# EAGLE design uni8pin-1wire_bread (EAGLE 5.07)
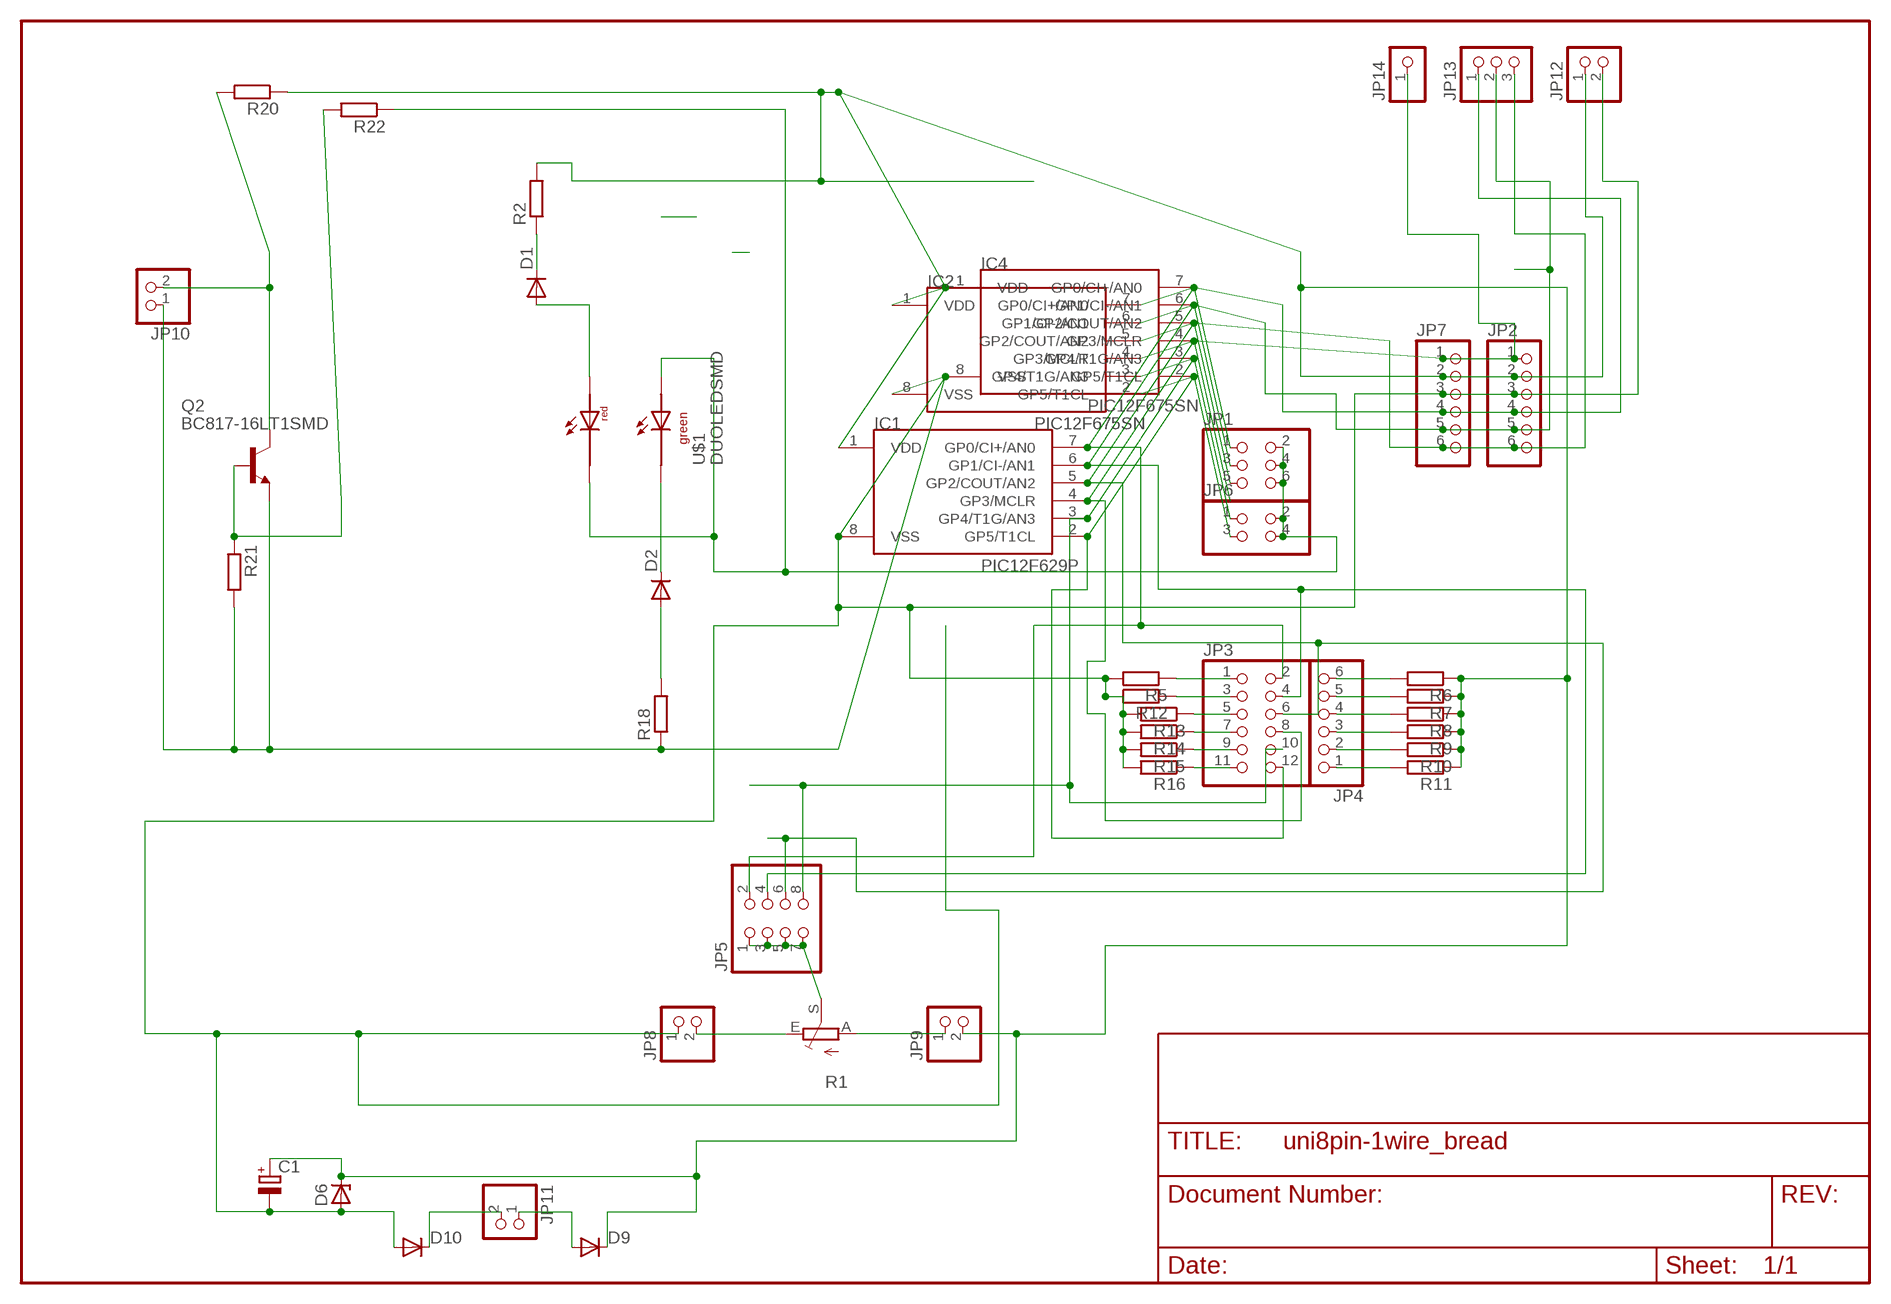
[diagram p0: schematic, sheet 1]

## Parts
C1  CPOL-EUE2.5-5  [E2,5-5]
D1  DIODE-MINIMELF  [MINIMELF]
D2  DIODE-MINIMELF  [MINIMELF]
D6  ZENER-DIODEZD-2.5  [ZDIO-2.5]
D9  DIODE-D-5  [D-5]
D10  DIODE-D-5  [D-5]
IC1  PIC12F629P  [DIL8]
IC2  PIC12F675SN  [SO-08]
IC4  PIC12F675SN  [SO-08]
JP1  PINHD-2X3  [2X03]
JP2  PINHD-1X6  [1X06]
JP3  PINHD-2X6  [2X06]
JP4  PINHD-1X6  [1X06]
JP5  PINHD-2X4  [2X04]
JP6  PINHD-2X2  [2X02]
JP7  PINHD-1X6  [1X06]
JP8  PINHD-1X2  [1X02]
JP9  PINHD-1X2  [1X02]
JP10  PINHD-1X2  [1X02]
JP11  PINHD-1X2  [1X02]
JP12  PINHD-1X2  [1X02]
JP13  PINHD-1X3  [1X03]
JP14  PINHD-1X1  [1X01]
Q2  BC817-16LT1SMD  [SOT23-BEC]
R1  TRIM_EU-RAND160  [RANDL]
R2  R-EU_R1206  [R1206]
R5  R-EU_R1206  [R1206]
R6  R-EU_R1206  [R1206]
R7  R-EU_R1206  [R1206]
R8  R-EU_R1206  [R1206]
R9  R-EU_R1206  [R1206]
R10  R-EU_R1206  [R1206]
R11  R-EU_R1206  [R1206]
R12  R-EU_R1206  [R1206]
R13  R-EU_R1206  [R1206]
R14  R-EU_R1206  [R1206]
R15  R-EU_R1206  [R1206]
R16  R-EU_R1206  [R1206]
R18  R-EU_R1206  [R1206]
R20  R-EU_R0805  [R0805]
R21  R-EU_R0805  [R0805]
R22  R-EU_R0805  [R0805]
U$1  DUOLEDSMD  [DUOLEDSMD]

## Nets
N$1: IC1.3(GP4/T1G/AN3) IC2.3(GP4/T1G/AN3) IC4.3(GP4/T1G/AN3) JP3.10 JP5.8 JP6.1
N$3: D1.C R2.1
N$4: JP1.2 JP1.4 JP1.6 JP6.2 JP6.4 R22.1 U$1.AGRN U$1.CRED
N$5: JP10.2 Q2.C R20.2
N$6: D2.C U$1.CGRN
N$8: D1.A U$1.ARED
N$9: IC1.2(GP5/T1CL) IC2.2(GP5/T1CL) IC4.2(GP5/T1CL) JP3.12 JP6.3
N$10: D2.A R18.2
N$11: IC1.4(GP3/MCLR) IC2.4(GP3/MCLR) IC4.4(GP3/MCLR) JP2.1 JP3.8 JP7.1 JP14.1
N$12: IC1.5(GP2/COUT/AN2) IC2.5(GP2/COUT/AN2) IC4.5(GP2/COUT/AN2) JP1.5 JP2.6 JP3.6 JP5.6 JP7.6 JP13.3
N$13: IC1.6(GP1/CI-/AN1) IC2.6(GP1/CI-/AN1) IC4.6(GP1/CI-/AN1) JP1.3 JP2.5 JP3.4 JP5.4 JP7.5 JP13.2
N$14: IC1.7(GP0/CI+/AN0) IC2.7(GP0/CI+/AN0) IC4.7(GP0/CI+/AN0) JP1.1 JP2.4 JP3.2 JP5.2 JP7.4 JP13.1
N$15: JP4.6 R6.2
N$16: JP5.1 JP5.3 JP5.5 JP5.7 R1.S
N$17: Q2.B R21.1 R22.2
N$18: JP3.1 R5.1
N$21: JP3.3 R12.1
N$22: JP3.5 R13.1
N$23: JP3.7 R14.1
N$24: JP3.9 R15.1
N$25: JP3.11 R16.1
N$26: JP4.5 R7.2
N$27: JP4.4 R8.2
N$28: JP4.3 R9.2
N$29: JP4.2 R10.2
N$30: JP4.1 R11.2
N$31: JP9.1 R1.A
N$32: JP8.2 R1.E
N$34: D10.C JP11.2
N$35: D9.A JP11.1
VDD: C1.+ D6.C D9.C IC1.1(VDD) IC2.1(VDD) IC4.1(VDD) JP2.2 JP7.2 JP9.2 JP12.1 R2.2 R6.1 R7.1 R8.1 R9.1 R10.1 R11.1 R20.1
VSS: C1.- D6.A D10.A IC1.8(VSS) IC2.8(VSS) IC4.8(VSS) JP2.3 JP7.3 JP8.1 JP10.1 JP12.2 Q2.E R5.2 R12.2 R13.2 R14.2 R15.2 R16.2 R18.1 R21.2

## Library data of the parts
C1 = rcl-2:CPOL-EU: POLARIZED CAPACITOR, European symbol
D1 D2 = diode:DIODE-: DIODE
D6 = diode-1:ZENER-DIODE: Z-Diode
D9 D10 = diode-1:DIODE-: DIODE
IC1 IC2 IC4 = microchip-5:PIC12F6*: uPC nW 1k Program Flash memory 2x Timer Comparator 10b A/D converter/ 4xIN
JP1 = pinhead(2):PINHD-2X3: PIN HEADER
JP2 JP7 = pinhead:PINHD-1X6: PIN HEADER
JP3 = pinhead(2):PINHD-2X6: PIN HEADER
JP4 = pinhead(2):PINHD-1X6: PIN HEADER
JP5 = pinhead(2):PINHD-2X4: PIN HEADER
JP6 = pinhead(2):PINHD-2X2: PIN HEADER
JP8-JP11 = pinhead(2):PINHD-1X2: PIN HEADER
JP12 = pinhead:PINHD-1X2: PIN HEADER
JP13 = pinhead:PINHD-1X3: PIN HEADER
JP14 = pinhead:PINHD-1X1: PIN HEADER
Q2 = transistor-npn:BC817*: NPN Transistor
R1 = pot:TRIM_EU-: POTENTIOMETER
R2 R18 = rcl:R-EU_: RESISTOR, European symbol
R5-R16 R20-R22 = rcl-2:R-EU_: RESISTOR, European symbol
U$1 = led:DUOLEDSMD

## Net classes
0 default: width 0.3 mm, drill 0.6 mm, clearance 0.2 mm
1 power: width 0.4 mm, drill 0.6 mm, clearance 0.2 mm

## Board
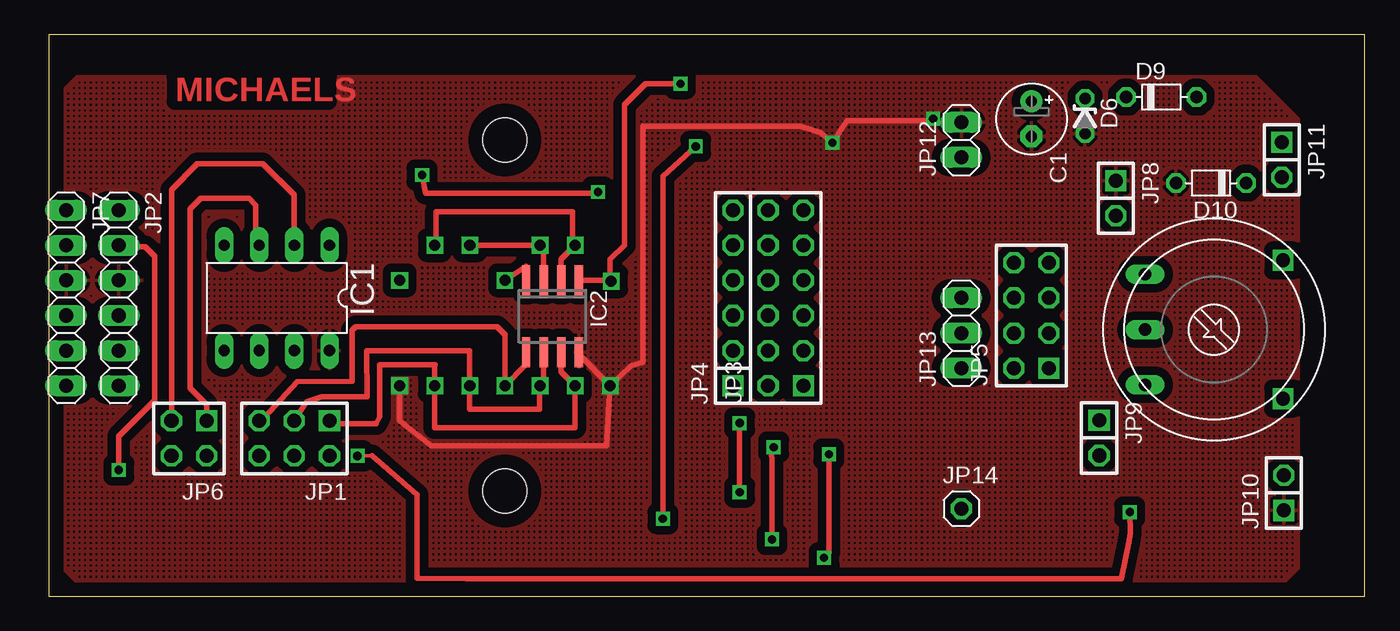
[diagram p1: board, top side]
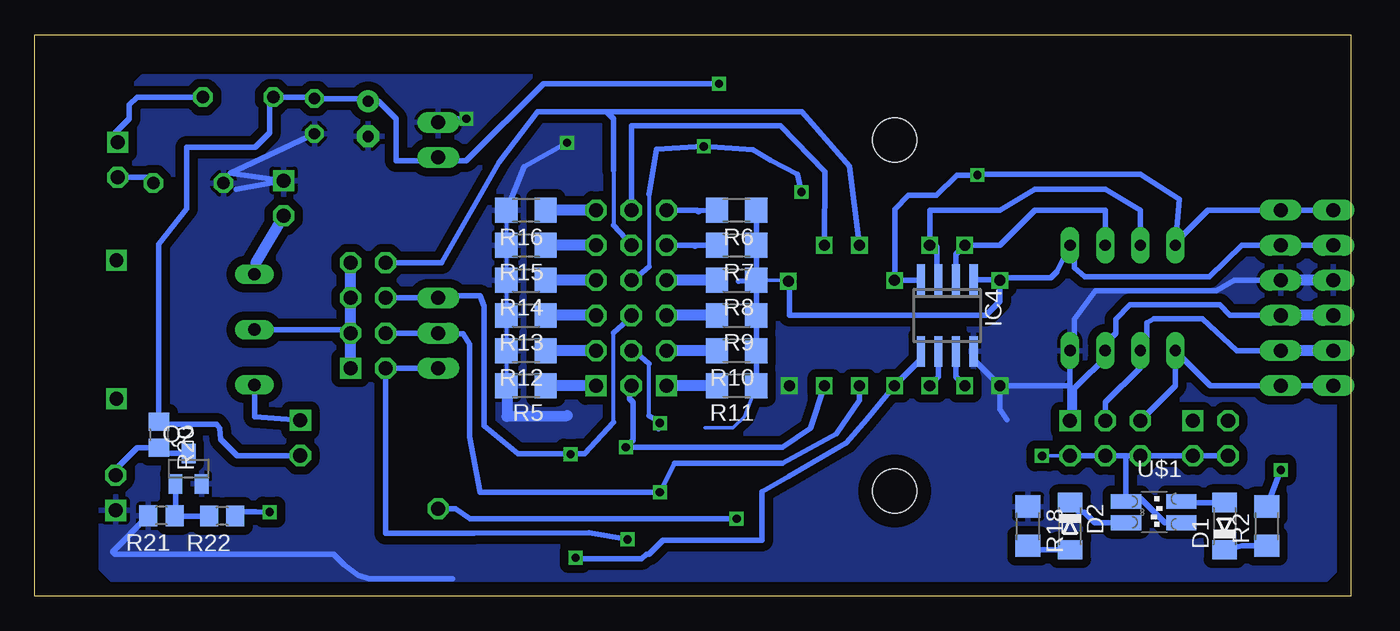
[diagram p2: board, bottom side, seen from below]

Size 95.25 x 40.64 mm. Coordinates in mm from the lower left corner, seen from the top.
Outline: 0,0 95.25,0 95.25,40.64 0,40.64 0,0
Copper layers (1*16): Top 0.035mm / dielectric 1.5mm / Bottom 0.035mm
Design rules "default": minimum track width 10mil, minimum drill 24mil, track to track 8mil, track to pad 8mil, pad to pad 8mil, via to via 8mil, smd to smd 8mil, copper to edge 40mil, drill to drill 8mil, minimum pad ring 10mil, minimum via ring 8mil, stop-mask expansion 4mil, vias tented up to drill 0mil, thermal gap 10mil
Holes 3.2 mm at 33.02,33.02 33.02,7.62

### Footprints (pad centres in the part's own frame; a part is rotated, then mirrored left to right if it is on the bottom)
E2,5-5 = drill 0.813 pad 1.6 round: + -1.27,0 | drill 0.813 pad 1.6 octagon: - 1.27,0
MINIMELF = smd 1.4 x 1.8: A 1.7,0; C -1.7,0
ZDIO-2.5 = drill 0.813 octagon: A 1.27,0; C -1.27,0
D-5 = drill 0.9 octagon: A 2.54,0; C -2.54,0
DIL8 = drill 0.813 long: 1 -3.81,-3.81; 2 -1.27,-3.81; 3 1.27,-3.81; 4 3.81,-3.81; 5 3.81,3.81; 6 1.27,3.81; 7 -1.27,3.81; 8 -3.81,3.81
SO-08 = smd 0.6 x 2.2: 1 -1.905,-2.6; 2 -0.635,-2.6; 3 0.635,-2.6; 4 1.905,-2.6; 5 1.905,2.6; 6 0.635,2.6; 7 -0.635,2.6; 8 -1.905,2.6
2X03 = drill 1.016 square: 1 -2.54,-1.27 | drill 1.016 octagon: 2 -2.54,1.27; 3 0,-1.27; 4 0,1.27; 5 2.54,-1.27; 6 2.54,1.27
1X06 = drill 1.016 long: 1 -6.35,0; 2 -3.81,0; 3 -1.27,0; 4 1.27,0; 5 3.81,0; 6 6.35,0
2X06 = drill 1.016 square: 1 -6.35,-1.27 | drill 1.016 octagon: 2 -6.35,1.27; 3 -3.81,-1.27; 4 -3.81,1.27; 5 -1.27,-1.27; 6 -1.27,1.27; 7 1.27,-1.27; 8 1.27,1.27; 9 3.81,-1.27; 10 3.81,1.27; 11 6.35,-1.27; 12 6.35,1.27
1X06' = drill 1.016 square: 1 -6.35,0 | drill 1.016 octagon: 2 -3.81,0; 3 -1.27,0; 4 1.27,0; 5 3.81,0; 6 6.35,0
2X04 = drill 1.016 square: 1 -3.81,-1.27 | drill 1.016 octagon: 2 -3.81,1.27; 3 -1.27,-1.27; 4 -1.27,1.27; 5 1.27,-1.27; 6 1.27,1.27; 7 3.81,-1.27; 8 3.81,1.27
2X02 = drill 1.016 square: 1 -1.27,-1.27 | drill 1.016 octagon: 2 -1.27,1.27; 3 1.27,-1.27; 4 1.27,1.27
1X02 = drill 1.016 square: 1 -1.27,0 | drill 1.016 octagon: 2 1.27,0
1X02' = drill 1.016 long: 1 -1.27,0; 2 1.27,0
1X03 = drill 1.016 long: 1 -2.54,0; 2 0,0; 3 2.54,0
1X01 = drill 1.016 octagon: 1 0,0
SOT23-BEC = smd 1 x 1.4: B -0.95,-1.1; C 0,1.1; E 0.95,-1.1
RANDL = drill 0.9 long: A -4,5; E 4,5; S 0,5 | drill 1 square: P$1 -5,-5; P$2 5,-5
R1206 = smd 1.6 x 1.803: 1 -1.422,0; 2 1.422,0
R0805 = smd 1.3 x 1.5: 1 -0.95,0; 2 0.95,0
DUOLEDSMD = smd 1.067 x 2.184: AGRN 0.77,1.95; ARED -0.77,1.95; CGRN 0.77,-2.05; CRED -0.77,-2.05

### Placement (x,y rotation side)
C1  71.12,34.54 270 top
D1  9.14,5.08 90 bottom
D2  20.32,5.08 270 bottom
D6  75,34.74 270 top
D9  80.52,36.12 0 top
D10  84.11,29.9 180 top
IC1  16.51,21.59 180 top
IC2  36.46,20.26 180 top
IC4  29.21,20.32 180 bottom
JP1  17.78,11.43 180 top
JP2  5.08,21.59 270 top
JP3  53.34,21.59 90 top
JP4  [1X06']  49.53,21.59 90 top
JP5  71.12,20.32 90 top
JP6  10.16,11.43 180 top
JP7  1.27,21.59 270 top
JP8  77.23,28.81 270 top
JP9  76.02,11.46 270 top
JP10  89.39,7.49 90 top
JP11  89.23,31.58 270 top
JP12  [1X02']  66.04,33.02 90 top
JP13  66.04,19.05 90 top
JP14  66.04,6.35 0 top
Q2  84.1,9.24 0 bottom
R1  84.33,19.3 90 top
R2  6.1,5.08 90 bottom
R5  59.69,15.24 180 bottom
R6  44.45,27.94 180 bottom
R7  44.45,25.4 180 bottom
R8  44.45,22.86 180 bottom
R9  44.45,20.32 180 bottom
R10  44.45,17.78 180 bottom
R11  44.45,15.24 180 bottom
R12  59.69,17.78 180 bottom
R13  59.69,20.32 180 bottom
R14  59.69,22.86 180 bottom
R15  59.69,25.4 180 bottom
R16  59.69,27.94 180 bottom
R18  23.37,5.08 270 bottom
R20  86.25,11.69 270 bottom
R21  86.07,5.84 180 bottom
R22  81.67,5.81 180 bottom
U$1  14.22,6.1 270 bottom

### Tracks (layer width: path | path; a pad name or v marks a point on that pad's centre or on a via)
N$1  (via drill 0.8)
  Top 0.406: JP6.1 11.43,13.86 10.25,15.04 10.25,28.04 11,28.79 14.5,28.79 15,28.29 15,25.79 14.97,25.82 IC1.3 | IC2.3 35.83,25.14 v35.56,25.4 v30.48,25.4
  Bottom 0.305: 53.34,30.83 53.34,26.83
  Bottom 0.406: JP3.10 52.07,25.44 53.34,26.83 | v35.56,25.4 36.27,31.1 39.71,35.05 53.85,35.05 | IC1.3 15.24,27.94 17.78,29.46 22.86,29.46 25.4,27.94 30.48,27.94 v30.48,25.4 30.11,25.4 29.96,25.25 29.96,23.04 IC4.3 | JP5.8 65.81,24.13 61.64,31.41 58.84,35.05 53.85,35.05 | 53.34,30.83 53.34,34.54 53.85,35.05
N$3
  Bottom 0.406: R2.1 7.85,3.66 D1.C
N$4  (via drill 0.6)
  Top 0.254: v22.35,10.16 23.4,10.17
  Top 0.406: 23.4,10.17 26.65,7.37 26.65,1.3 30.23,1.27 77.62,1.27 78.17,3.9 78.28,4.56 v78.23,6.1
  Bottom 0.254: JP1.2 v22.35,10.16
  Bottom 0.406: v78.23,6.1 79.26,6.11 80.42,6.11 R22.1 | JP1.6 15.06,9.98 | 16.26,10.16 JP1.6 | 16.26,10.16 JP1.4 JP1.2 | JP6.4 JP6.2 JP1.6 | U$1.AGRN 13.45,5.33 15.24,7.11 16.03,7.11 U$1.CRED 16.27,10.14 16.26,10.16
N$5
  Bottom 0.406: Q2.C 85.85,10.34 R20.2 87.81,10.74 89.41,9.14 89.41,8.78 JP10.2
N$6
  Bottom 0.406: U$1.CGRN 18.53,5.33 19.3,6.1 19.64,6.1 D2.C
N$8
  Bottom 0.406: D1.A 12.19,6.78 U$1.ARED
N$9  (via drill 0.8)
  Top 0.406: IC2.2 37.09,24.39 v38.1,25.4 37.9,25.6 37.9,27.82 28.03,27.82 28.03,25.49 v27.94,25.4 | JP6.3 8.89,29.43 10.75,31.29 15.5,31.29 17.75,29.04 17.75,26.54 18,26.29 17.51,25.8 | 17.51,25.8 17.5,25.79 | 17.51,25.8 IC1.2
  Bottom 0.406: v38.1,25.4 38.06,30.73 41.27,34.04 52.07,34.04 JP3.12 | IC4.2 28.57,24.77 v27.94,25.4 25.4,25.4 22.86,27.94 17.78,27.94 IC1.2
N$10
  Bottom 0.406: D2.A 23.09,3.38 R18.2
N$11  (via drill 0.6, 0.8)
  Top 0.406: IC2.4 34.55,23.86 v33.02,22.86 | v44.45,5.62 44.45,30.41 v46.83,32.55 | v39.75,29.25 39.28,29.15 27.28,29.15 v27.02,30.48
  Bottom 0.305: 50.8,29.08 50.8,23.83
  Bottom 0.406: 12.43,25.86 12.5,25.79 | 12.43,25.86 IC1.4 12.43,28.72 15.25,30.52 26.73,30.52 26.77,30.48 v27.02,30.48 28.52,30.48 30,29 32,29 33,28 33,22.88 v33.02,22.86 31.18,22.86 IC4.4 | 12.43,25.86 10.35,27.94 JP2.1 JP7.1 | JP3.8 51.93,22.86 50.8,23.83 | JP14.1 64.77,6.35 63.75,5.62 v44.45,5.62 | v39.75,29.25 40.04,30.54 42,31.56 43.27,32.32 v46.83,32.55 50.25,32.33 50.8,29.08
N$12  (via drill 0.6, 0.8)
  Top 0.406: IC2.5 34.55,16.77 v33.02,15.24 | 33.04,15.04 33.02,15.06 v33.02,15.24 | v33.02,15.24 33.02,18.94 32.46,19.5 22.21,19.5 21.96,19.25 21.96,15.57 18,15.54 15.25,12.54 15.24,12.54 JP1.5 | v56.46,10.29 56.46,3.14 v56.11,2.79
  Bottom 0.305: 53.34,12.58 53.34,19.08
  Bottom 0.406: 56.42,10.33 60.25,10.33 62.74,12.33 62.74,21 63,21.75 65.88,21.75 JP13.3 JP5.6 | 53.34,12.58 55.46,10.33 56.42,10.33 | JP3.6 52.07,20.22 53.34,19.08 | IC4.5 31.11,17.14 v33.02,15.24 35.05,12.79 36.5,11.1 40.66,8.68 42.63,7.58 42.63,4.06 49.78,4.06 50.8,3.05 50.98,3.05 51.32,2.71 56.03,2.71 v56.11,2.79 | JP7.6 JP2.6 10.16,15.24 IC1.5 12.7,15.24 JP1.5 | v56.46,10.29 56.42,10.33
N$13  (via drill 0.6, 0.8)
  Top 0.406: IC2.6 35.83,15.51 v35.56,15.24 35.59,15.24 35.79,15.04 35.54,14.79 35.54,13.54 30.48,13.54 v30.48,15.24 30.48,17.78 23.01,17.78 23.05,14.46 19.74,14.46 18.68,14.08 JP1.3 | v50,7.54 v50,12.54
  Bottom 0.305: 50.8,13.08 50.8,16.83
  Bottom 0.406: JP2.5 8.24,17.78 10.75,20.07 14.25,20.07 14.75,19.79 14.75,18.79 15.13,18.41 | 15.13,18.41 15.25,18.29 15.25,16.54 17.75,14.04 17.75,12.54 17.78,12.57 JP1.3 | 15.13,18.41 IC1.6 | 52.07,17.44 JP3.4 52.01,17.78 51.96,17.83 50.8,16.83 | IC4.6 29.84,15.88 v30.48,15.24 | 50.8,13.08 50.05,12.63 50.09,12.13 v50,12.54 | 35.83,15.51 v35.56,15.24 35.56,14.19 37.22,11.77 41.13,9.65 48.94,9.65 v50,7.54 63,7.54 63.75,11.54 63.75,18.25 64.25,19 65.99,19 JP13.2 | JP13.2 JP5.4 | 64.75,19.25 65.84,19.25 JP13.2
  Bottom 0.813: JP7.5 JP2.5
N$14  (via drill 0.6, 0.8)
  Top 0.406: IC2.7 37.09,16.25 v38.1,15.24 v38.1,15.23 38.29,15.04 38.1,14.85 | 38.1,14.85 38.04,14.79 | 38.1,14.85 38.1,12.2 27.94,12.2 v27.94,15.24 27.94,16.73 27.96,16.75 23.96,16.75 23.96,13 23.71,12.5 20.52,12.5 JP1.1 | v52.34,4.12 52.34,9.7 52.3,10.45 v52.46,10.79
  Bottom 0.406: JP2.4 8.78,20.32 9.5,21.08 16,21.08 17,20.04 17,19.04 17.51,18.53 IC1.7 17.51,17.53 20,15.04 20,13.04 20.32,12.72 JP1.1 | IC4.7 28.57,15.88 v27.94,15.24 | v52.34,4.12 55.13,4.6 63.46,4.56 69.84,4.56 69.85,4.58 JP5.2 JP13.1 | 52.21,15.1 52.21,14.29 51.96,14.04 51.96,11.29 v52.46,10.79 44.72,10.79 41.11,10.78 39.12,12.15 v38.1,15.24
  Bottom 0.813: JP7.4 JP2.4 | 52.21,15.1 JP3.2
N$15
  Bottom 0.406: R6.2 47.14,27.9 47.21,27.83 47.32,27.94 JP4.6
N$16
  Bottom 0.406: R1.S 72.64,19.3 JP5.3
  Bottom 0.813: 72.58,24.13 JP5.7 JP5.5 JP5.3 JP5.1
N$17
  Bottom 0.406: R22.2 85.09,5.81 R21.1 85.05,5.91 Q2.B
N$18
  Bottom 0.813: JP3.1 R5.1
N$21
  Bottom 0.813: JP3.3 R12.1
N$22
  Bottom 0.813: JP3.5 R13.1
N$23
  Bottom 0.813: JP3.7 R14.1
N$24
  Bottom 0.813: JP3.9 R15.1
N$25
  Bottom 0.813: JP3.11 R16.1
N$26
  Bottom 0.406: R7.2 47.39,25.4 47.46,25.33 47.53,25.4 JP4.5
N$27
  Bottom 0.813: R8.2 JP4.4
N$28
  Bottom 0.813: R9.2 JP4.3
N$29
  Bottom 0.813: R10.2 JP4.2
N$30
  Bottom 0.813: R11.2 JP4.1
N$31
  Bottom 0.406: R1.A 79.33,13 JP9.1
N$32
  Bottom 0.406: R1.E 79.33,24.04 79.24,24.13
  Bottom 0.813: 79.24,24.13 JP8.2
N$34
  Bottom 0.406: JP11.2 87.06,30.31 D10.C
N$35
  Bottom 0.406: D9.A 87.83,36.12 88.39,35.56 88.39,34.54 89.41,33.53 89.41,33.02 JP11.1
VDD  (via drill 0.6, 0.8)
  Top 0.406: 38.37,23.12 IC2.1 40.71,22.86 v40.71,22.79 40.64,22.86 40.64,24.38 41.66,25.4 41.66,35.56 43.18,37.08 v45.72,37.08 | 5,25.29 7,25.29 7.68,24.61 7.68,14.18 5.08,11.58 v5.08,9.14 | 5,25.29 4.75,25.29 4.5,25.54 4.75,25.54 5,25.29 | 5,25.29 5.08,25.37 JP2.2
  Bottom 0.254: R8.1 40.78,22.86 v40.71,22.79 | R11.1 43.9,13 44.7,12.19 46.74,12.19
  Bottom 0.406: JP7.2 JP2.2 7.89,25.4 10.25,23.11 19.25,23.11 20,23.79 20,25.54 20.25,25.79 20.05,25.99 IC1.1 21.26,23.49 21.71,23.04 25.4,23.04 v25.4,22.86 | IC4.1 25.46,22.92 v25.4,22.86 | R8.1 44.3,22.79 | v25.4,22.86 25.4,21.34 26.42,20.32 40.64,20.32 40.64,22.72 v40.71,22.79 | R11.1 R10.1 R9.1 R8.1 | R8.1 R7.1 R6.1 | R2.2 v5.08,9.14 | JP9.2 80.58,10.19 81.77,11.38 81.84,12.17 82.08,12.47 86.03,12.47 R20.1 86.25,25.46 84.25,28.06 84.25,32.48 79.28,32.48 78.23,33.53 78.23,35.87 D9.C 75.11,36.12 D6.C 71.31,36.01 C1.+ 70.36,35.81 69.09,34.54 69.09,31.5 66.29,31.5 JP12.1 65.79,31.5 64.01,31.5 58.42,37.08 v45.72,37.08
VSS  (via drill 0.6, 0.8)
  Top 0.406: IC2.8 38.37,17.52 v40.64,15.24 | v40.64,15.24 42.14,16.69 43,16.94 43,34 54.39,34 55.88,33.53 v56.72,32.81 57.78,34.41 64.01,34.41 v64.01,34.54 | v25.4,15.24 25.4,12.7 27.69,10.91 40.39,10.91 v40.64,15.24
  Bottom 0.254: R5.2 R12.2 R13.2 R14.2 R15.2 R16.2
  Bottom 0.406: JP2.3 8.43,22.86 9.75,22.1 18.5,22.1 20,20.04 20,18.1 IC1.8 20.32,15.24 | 40.54,15.29 40.59,15.24 v40.64,15.24 | R16.2 59.84,31.09 v56.72,32.81 | IC4.8 27.3,17.14 v25.4,15.24 | 20.32,15.24 20.32,13.1 | 20.32,15.24 v25.4,15.24 | 65,1.27 71.04,1.29 71.85,1.54 72.84,2.28 73.61,3.05 89.41,3.05 89.6,3.24 R21.2 | v25.4,15.24 25.4,13.54 24.88,12.79 | 80.67,29.46 JP8.1 81.09,30.62 D6.A | v64.01,34.54 66.04,34.54 JP12.2
  Bottom 0.813: JP7.3 JP2.3 | R5.2 61.08,15.19 61.08,13.03 56.71,13.08
  pour Bottom (isolate 0.61, rank 5): 1.02,36.58 1.02,2.03 3.05,0 88.39,0 90.42,2.03 90.42,34.54 87.38,37.59 2.03,37.59
  pour Top (isolate 0.61, rank 5, hatched): 1.02,36.58 1.02,2.03 3.05,0 88.39,0 90.42,2.03 90.42,34.54 87.38,37.59 2.03,37.59

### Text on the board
Top: MICHAELS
